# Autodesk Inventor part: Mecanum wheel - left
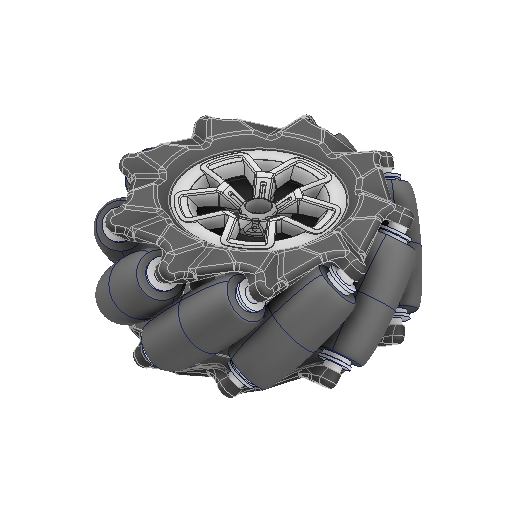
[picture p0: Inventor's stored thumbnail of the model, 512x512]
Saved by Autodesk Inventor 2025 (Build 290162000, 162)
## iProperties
Created: 2024-11
Part Number: Mecanum wheel - left
Material: Generico
Description: STEP AP214
Document SubType Name: Modeling
Designer: R5800u
Density: 1 g/cm^3
Appearance: Default
Title: Mecanum wheel - left.STEP
Sending System: SolidWorks 2022
Preprocessor: SwSTEP 2.0
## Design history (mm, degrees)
feature "Половина колеса Mecanum_Верхняя половина - левая_1:1"
feature "Половина колеса Mecanum_Нижняя половина - левая_2:1"
feature "Ролик колеса Mecanum_3:1"
feature "Ролик колеса Mecanum_4:1"
feature "Ролик колеса Mecanum_5:1"
feature "Ролик колеса Mecanum_6:1"
feature "Ролик колеса Mecanum_7:1"
feature "Ролик колеса Mecanum_8:1"
feature "Ролик колеса Mecanum_9:1"
feature "Ролик колеса Mecanum_10:1"
feature "Ролик колеса Mecanum_11:1"
feature "Декоративная накладка_12:1"
node "Solido1"
node "Solido2"
node "Solido3"
node "Solido4"
node "Solido5"
node "Solido6"
node "Solido7"
node "Solido8"
node "Solido9"
node "Solido10"
node "Solido11"
node "Solido12"
